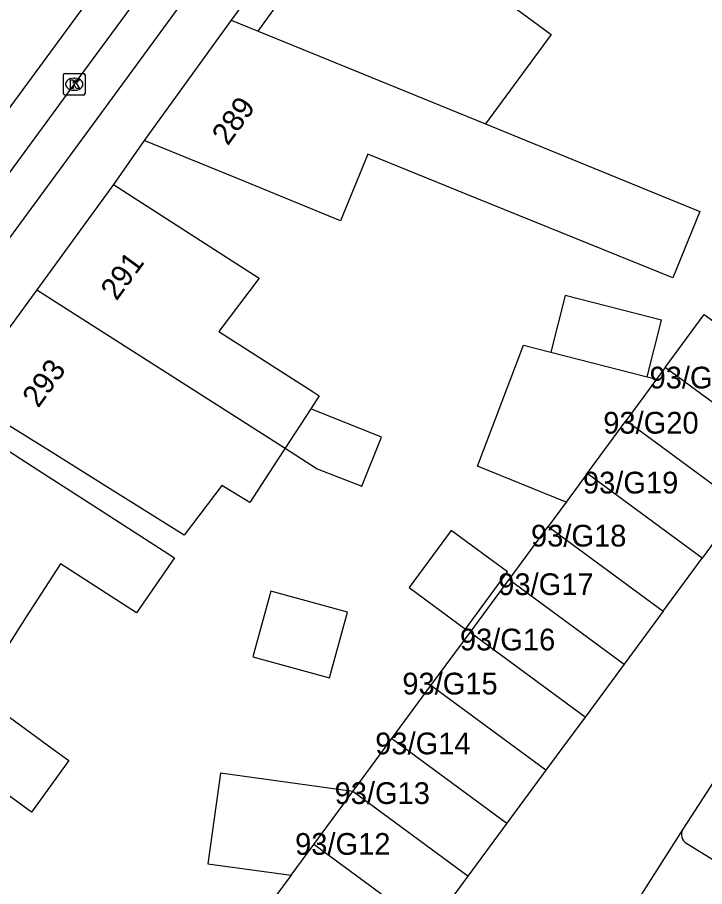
# Model space of a CAD drawing. Extents: x 160557 to 161245, y 385330 to 386505.
# Drawn here: x 161001.82 to 161033.44, y 385993.65 to 386033.63 of the extents above; entities that cross this region are included whole.
import ezdxf

# ---------------------------------------------------------------- set-up
doc = ezdxf.new("R2010")
doc.units = 0
for name, color, linetype in [('IMGEO_Kolk', 7, 'Continuous'), ('IMGEO_Pand', 7, 'Continuous'), ('IMGEO_Pand_nummerreeks', 7, 'Continuous'), ('IMGEO_Rijbaan_lokaal_gesloten', 7, 'Continuous'), ('IMGEO_Rijbaan_lokaal_open', 7, 'Continuous'), ('IMGEO_Voetpad_open', 7, 'Continuous')]:
    doc.layers.add(name, color=color, linetype=linetype)

msp = doc.modelspace()

# ---------------------------------------------------------------- linework, layer by layer
at = {"layer": 'IMGEO_Kolk'}
for p, q in [((161003.933, 386030.128), (161003.933, 386030.98)), ((161004.008, 386031.054), (161004.86, 386031.054)), ((161004.421, 386030.834), (161004.446, 386030.834)), ((161004.934, 386030.98), (161004.934, 386030.128)), ((161004.86, 386030.054), (161004.008, 386030.054)), ((161004.444, 386030.274), (161004.419, 386030.274))]:
    msp.add_line(p, q, dxfattribs=at)
for points in [[(161003.933, 386030.128), (161003.933, 386030.98)], [(161004.008, 386031.054), (161004.86, 386031.054)], [(161004.254, 386030.754), (161004.377, 386030.754), (161004.377, 386030.603), (161004.507, 386030.754), (161004.671, 386030.754), (161004.525, 386030.603), (161004.678, 386030.354), (161004.526, 386030.354), (161004.441, 386030.518), (161004.377, 386030.451), (161004.377, 386030.354), (161004.254, 386030.354), (161004.254, 386030.754)], [(161004.934, 386030.98), (161004.934, 386030.128)], [(161004.86, 386030.054), (161004.008, 386030.054)]]:
    msp.add_lwpolyline(points, dxfattribs=at)
for centre, start, end in [((161004.01, 386030.978), 91.552, 178.448), ((161004.01, 386030.978), 91.552, 178.448), ((161004.858, 386030.978), 1.552, 88.448), ((161004.858, 386030.978), 1.552, 88.448), ((161004.01, 386030.13), 181.552, 268.448), ((161004.01, 386030.13), 181.552, 268.448), ((161004.858, 386030.13), 271.552, 358.448), ((161004.858, 386030.13), 271.552, 358.448)]:
    msp.add_arc(centre, 0.0765, start, end, dxfattribs=at)
for centre, major_axis, ratio, start_param, end_param in [((161004.42, 386030.554), (-0.387, 0.002), 0.722429, 4.712389, 7.853982), ((161004.445, 386030.554), (-0.39, 0.002), 0.717154, 1.570796, 4.712389)]:
    msp.add_ellipse(centre, major_axis=major_axis, ratio=ratio, start_param=start_param, end_param=end_param, dxfattribs=at)
at = {"layer": 'IMGEO_Pand'}
for points in [[(161012.89, 386032.99), (161015.833, 386037.096), (161015.583, 386037.279), (161018.894, 386041.785)], [(161025.71, 386036.754), (161024.073, 386034.527), (161024.976, 386033.864), (161026.37, 386032.841), (161023.35, 386028.728)], [(161011.65, 386033.496), (161007.646, 386027.97)], [(161011.65, 386033.496), (161012.89, 386032.99)], [(161012.89, 386032.99), (161021.697, 386029.403), (161023.35, 386028.728)], [(161023.35, 386028.728), (161024.21, 386028.377), (161033.212, 386024.706), (161031.969, 386021.643), (161022.962, 386025.303), (161017.939, 386027.344), (161016.685, 386024.276), (161012.275, 386026.078), (161007.646, 386027.97)], [(161006.245, 386025.935), (161002.708, 386021.095)], [(161006.245, 386025.935), (161010.449, 386023.228), (161012.934, 386021.628), (161011.089, 386019.174), (161015.431, 386016.398), (161015.704, 386016.224), (161015.315, 386015.627)], [(161002.708, 386021.095), (161000, 386017.389), (160999.171, 386016.255)], [(161002.708, 386021.095), (161014.132, 386013.81)], [(161030.788, 386017.094), (161031.454, 386019.707), (161027.023, 386020.836), (161026.357, 386018.226)], [(161031.623, 386017.526), (161033.419, 386019.964), (161034.022, 386019.52)], [(161027.062, 386011.336), (161022.984, 386012.983), (161025.107, 386018.546), (161026.357, 386018.226)], [(161026.357, 386018.226), (161030.788, 386017.094)], [(161031.623, 386017.526), (161031.223, 386016.983)], [(161036.913, 386013.628), (161031.623, 386017.526)], [(161031.223, 386016.983), (161029.827, 386015.089)], [(161030.788, 386017.094), (161031.223, 386016.983)], [(161014.132, 386013.81), (161013.76, 386013.239), (161012.505, 386011.312), (161011.223, 386012.102), (161009.495, 386009.82), (161005.938, 386012.037), (161003.415, 386013.61), (161000, 386015.738), (160999.171, 386016.255)], [(161015.315, 386015.627), (161014.132, 386013.81)], [(161014.132, 386013.81), (161015.605, 386012.87), (161017.666, 386012.065), (161018.572, 386014.32), (161015.315, 386015.627)], [(160998.604, 386015.488), (161000, 386014.591), (161002.81, 386012.785), (161005.542, 386011.028), (161009.047, 386008.775), (161007.297, 386006.24), (161003.797, 386008.49), (161002.222, 386006.05), (161000.666, 386003.638), (160993.361, 386008.352)], [(161028.031, 386012.652), (161029.827, 386015.089)], [(161029.827, 386015.089), (161035.117, 386011.191)], [(161028.031, 386012.652), (161027.062, 386011.336)], [(161033.321, 386008.753), (161028.031, 386012.652)], [(161027.062, 386011.336), (161026.235, 386010.214)], [(161035.117, 386011.191), (161033.321, 386008.753)], [(161019.845, 386007.402), (161022.431, 386005.496), (161024.365, 386008.119), (161021.778, 386010.025), (161019.845, 386007.402)], [(161024.439, 386007.777), (161026.235, 386010.214)], [(161026.235, 386010.214), (161031.525, 386006.316)], [(161031.525, 386006.316), (161033.321, 386008.753)], [(160992.872, 386007.689), (160996.913, 386004.745), (161000, 386002.495), (161003.424, 386000), (161004.191, 385999.441), (161002.466, 385997.074), (161000, 385998.871), (160998.451, 386000), (160997.789, 386000.482), (160997.438, 386000), (160994.121, 385995.449)], [(161022.643, 386005.34), (161024.439, 386007.777)], [(161024.439, 386007.777), (161029.729, 386003.879)], [(161012.65, 386004.21), (161016.177, 386003.246), (161017.004, 386006.27), (161013.477, 386007.234), (161012.65, 386004.21)], [(161031.525, 386006.316), (161029.729, 386003.879)], [(161020.847, 386002.903), (161022.643, 386005.34)], [(161027.933, 386001.442), (161022.643, 386005.34)], [(161029.729, 386003.879), (161027.933, 386001.442)], [(161019.051, 386000.465), (161020.847, 386002.903)], [(161026.137, 385999.004), (161020.847, 386002.903)], [(161027.933, 386001.442), (161026.871, 386000), (161026.137, 385999.004)], [(161017.255, 385998.028), (161018.708, 386000), (161019.051, 386000.465)], [(161019.051, 386000.465), (161024.341, 385996.567)], [(161017.255, 385998.028), (161011.162, 385998.87), (161010.585, 385994.698), (161014.411, 385994.169)], [(161026.137, 385999.004), (161024.341, 385996.567)], [(161015.459, 385995.591), (161017.255, 385998.028)], [(161022.545, 385994.13), (161017.255, 385998.028)], [(161024.341, 385996.567), (161022.545, 385994.13)], [(161014.411, 385994.169), (161015.459, 385995.591)], [(161020.75, 385991.692), (161015.459, 385995.591)], [(161014.411, 385994.169), (161013.663, 385993.154)], [(161022.545, 385994.13), (161020.75, 385991.692)]]:
    msp.add_lwpolyline(points, dxfattribs=at)
at = {"layer": 'IMGEO_Rijbaan_lokaal_gesloten'}
for points in [[(160976.7, 385995.799), (161003.024, 386031.591), (161028.434, 386066.217)], [(161029.852, 386065.192), (161027.941, 386062.559), (161016.115, 386046.431), (161004.434, 386030.555), (161000, 386024.524), (160990.279, 386011.323), (160981.972, 386000), (160979.051, 385996.019), (160978.106, 385994.757)]]:
    msp.add_lwpolyline(points, dxfattribs=at)
at = {"layer": 'IMGEO_Rijbaan_lokaal_open'}
for points in [[(161032.442, 385996.293), (161034.254, 385999.08)], [(161019.362, 385975.725), (161032.442, 385996.293)]]:
    msp.add_lwpolyline(points, dxfattribs=at)
at = {"layer": 'IMGEO_Voetpad_open'}
for points in [[(161031.343, 386064.18), (161017.583, 386045.505), (161013.44, 386039.843), (161010.768, 386036.201), (161005.853, 386029.488), (161004.076, 386027.06), (161000, 386021.52), (160993.034, 386012.051), (160990.8, 386009.037), (160985.764, 386002.174), (160984.169, 386000), (160982.2, 385997.316), (160979.543, 385993.676)], [(161028.406, 386056.312), (161011.65, 386033.496)], [(161007.646, 386027.97), (161006.245, 386025.935)], [(161032.617, 385995.626), (161035.482, 385993.862)]]:
    msp.add_lwpolyline(points, dxfattribs=at)
msp.add_arc((161032.845, 385996.042), 0.475, 148.149, 241.2536, dxfattribs=at)

# ---------------------------------------------------------------- texts
at = {"layer": 'IMGEO_Pand_nummerreeks'}
for s, rotation, p in [('289', 54.0758, (161011.496, 386027.692)), ('291', 53.8408, (161006.378, 386020.558)), ('293', 53.8408, (161002.774, 386015.627))]:
    msp.add_text(s, height=1, rotation=rotation, dxfattribs=at).set_placement(p)
for s, p in [('93/G21', (161030.903, 386016.561)), ('93/G20', (161028.774, 386014.483)), ('93/G19', (161027.839, 386011.73)), ('93/G18', (161025.45, 386009.289)), ('93/G17', (161023.943, 386007.056)), ('93/G16', (161022.177, 386004.511)), ('93/G15', (161019.529, 386002.485)), ('93/G14', (161018.282, 385999.732)), ('93/G13', (161016.412, 385997.447)), ('93/G12', (161014.594, 385995.11))]:
    msp.add_text(s, height=1, dxfattribs=at).set_placement(p)

doc.saveas('drawing.dxf')
